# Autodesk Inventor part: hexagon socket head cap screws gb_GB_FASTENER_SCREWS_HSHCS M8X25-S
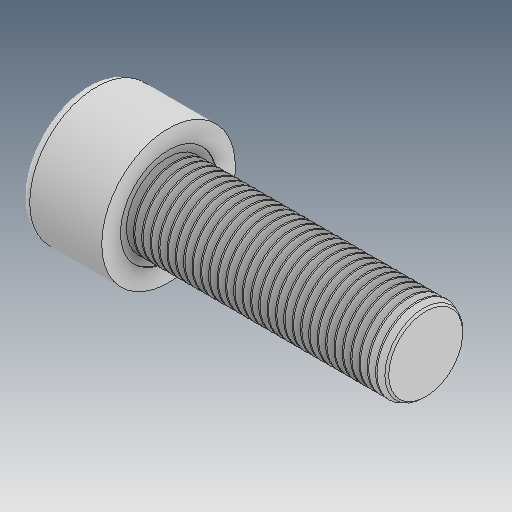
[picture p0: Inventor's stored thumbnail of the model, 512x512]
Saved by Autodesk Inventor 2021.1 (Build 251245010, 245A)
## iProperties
Created: 2013-04
Part Number: hexagon socket head cap screws gb_GB_FASTENER_SCREWS_HSHCS M8X25-S
Material: Ogólny
Document SubType Name: Modeling
Designer: user
Density: 1 g/cm^3
Appearance: Domyślna
Author: user
Revision Number: ÈÎºÎ
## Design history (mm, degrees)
feature "LPattern10"
node "Bryła1"
